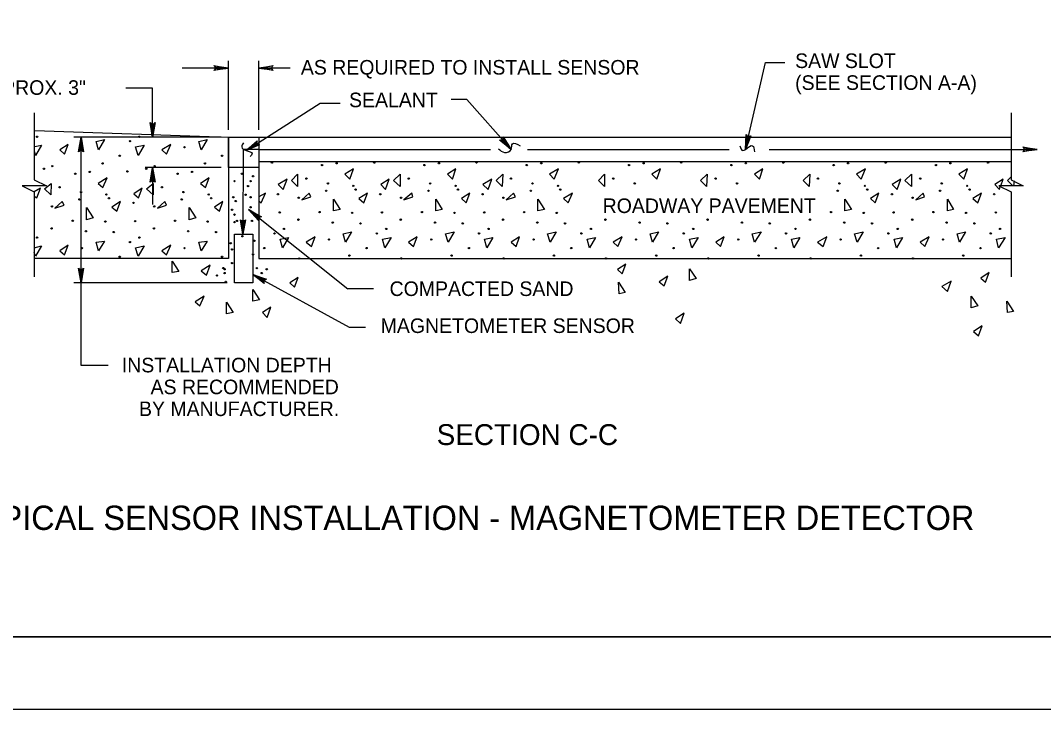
# Model space of a CAD drawing. Extents: x 2709 to 3899, y 22 to 1210.
# Drawn here: x 2819.9 to 3030.6, y 22.2 to 164.1 of the extents above; entities that cross this region are included whole.
import ezdxf

# ---------------------------------------------------------------- set-up
doc = ezdxf.new("R2010")
doc.units = 0
for name, color, linetype in [('1', 7, 'Continuous'), ('2', 7, 'Continuous'), ('3', 7, 'Continuous'), ('PLT-BNDY', 7, 'Continuous')]:
    doc.layers.add(name, color=color, linetype=linetype)

# ---------------------------------------------------------------- blocks, each defined once
blk = doc.blocks.new('RARROW')
at = {"layer": '3'}
blk.add_lwpolyline([(-2.2695, 0.285), (-2.184875, 0.12075), (0, 0), (-2.2695, 0.285), (-2.38575, 0.384625), (0, 0), (-2.183125, -0.108), (-2.262875, -0.2705), (0, 0), (-2.38575, -0.379125), (-2.262875, -0.2705)], dxfattribs=at)

msp = doc.modelspace()

# ---------------------------------------------------------------- linework, layer by layer
at = {"layer": '1'}
for p, q in [((3534.86, 37.17), (2748.86, 37.17)), ((2748.86, 37.17), (3334.86, 37.17))]:
    msp.add_line(p, q, dxfattribs=at)
at = {"layer": '2'}
for p, q in [((2862.72, 154.29), (2853.22, 154.29)), ((2862.72, 141.54), (2862.72, 155.79)), ((2868.97, 141.54), (2868.97, 155.79)), ((2875.47, 154.29), (2868.97, 154.29)), ((2969.22, 137.54), (2973.35, 155.41)), ((2973.35, 155.41), (2977.35, 155.41)), ((2847.1, 150.16), (2841.6, 150.16)), ((2847.1, 140.04), (2847.1, 150.16)), ((2911.85, 147.79), (2908.6, 147.79)), ((2920.97, 137.54), (2911.85, 147.79)), ((2866.35, 137.29), (2881.6, 147.04)), ((2881.6, 147.04), (2885.72, 147.04)), ((2861.22, 140.04), (2830.85, 140.04)), ((2832.35, 110.04), (2832.35, 140.04)), ((2861.22, 140.04), (2845.6, 140.04)), ((2868.97, 140.04), (2868.97, 115.04)), ((2861.22, 133.79), (2845.6, 133.79)), ((2847.1, 133.79), (2847.1, 126.16)), ((2866.85, 125.16), (2887.35, 108.79)), ((2867.72, 111.79), (2887.6, 100.91)), ((2862.47, 110.04), (2830.85, 110.04)), ((2832.35, 93.04), (2832.35, 110.04)), ((2892.6, 108.79), (2887.35, 108.79)), ((2887.6, 100.91), (2890.97, 100.91)), ((2837.97, 93.04), (2832.35, 93.04))]:
    msp.add_line(p, q, dxfattribs=at)
for points in [[(2822.72, 145.04), (2822.72, 131.29), (2825.22, 130.04), (2820.22, 130.04), (2822.72, 128.79), (2822.72, 111.29)], [(3023.97, 145.04), (3023.97, 131.29), (3026.47, 130.04), (3021.47, 130.04), (3023.97, 128.79), (3023.97, 111.29)], [(2822.85, 141.41), (2862.72, 140.04)], [(2862.72, 140.04), (2862.72, 115.04), (2822.72, 115.04)], [(2862.72, 140.04), (2868.97, 140.04), (2868.97, 133.79), (2862.72, 133.79), (2862.72, 140.04)], [(2868.97, 140.04), (3023.97, 140.04)], [(2822.85, 138.16), (2824.22, 138.41)], [(2822.97, 136.29), (2822.85, 137.04)], [(2824.22, 138.41), (2822.97, 136.29)], [(2868.97, 137.54), (2865.73, 137.53), (2865.72, 120.04)], [(2868.97, 137.54), (2916.72, 137.54)], [(2924.35, 137.54), (2965.85, 137.54)], [(2974.1, 137.54), (3029.35, 137.54)], [(2868.97, 135.04), (3023.97, 135.04)], [(3022.35, 131.41), (3020.6, 130.29)], [(3021.85, 130.04), (3022.35, 131.41)], [(3023.22, 131.16), (3023.97, 131.91)], [(3024.35, 130.04), (3023.22, 131.16)], [(3024.6, 131.04), (3024.47, 130.04)], [(2823.97, 129.54), (2822.72, 128.79)], [(2823.22, 127.54), (2823.97, 129.54)], [(2824.85, 129.41), (2826.22, 130.54)], [(2826.1, 128.16), (2824.85, 129.41)], [(2826.22, 130.54), (2826.1, 128.16)], [(3020.6, 130.29), (3021.6, 129.29)], [(3021.6, 129.29), (3021.72, 129.91)], [(2822.72, 127.91), (2823.22, 127.54)], [(2870.35, 128.54), (2868.97, 127.79)], [(2868.97, 126.91), (2869.47, 126.54)], [(2869.47, 126.54), (2870.35, 128.54)], [(2822.72, 117.29), (2824.22, 117.66)], [(2822.97, 115.54), (2822.72, 116.29)], [(2824.22, 117.66), (2822.97, 115.54)], [(2868.97, 115.04), (3023.97, 115.04)]]:
    msp.add_lwpolyline(points, dxfattribs=at)
for points in [[(2835.47, 139.16), (2837.22, 139.54), (2835.97, 137.41)], [(2856.6, 139.16), (2858.35, 139.54), (2857.1, 137.41)], [(2829.72, 138.54), (2827.97, 137.41), (2828.97, 136.54)], [(2843.6, 138.04), (2845.35, 138.41), (2844.1, 136.29)], [(2850.85, 138.54), (2848.97, 137.41), (2849.97, 136.54)], [(2888.47, 133.54), (2886.72, 132.41), (2887.72, 131.41)], [(2909.6, 133.54), (2907.85, 132.41), (2908.85, 131.41)], [(2930.72, 133.54), (2928.85, 132.41), (2929.85, 131.41)], [(2951.72, 133.54), (2949.97, 132.41), (2950.97, 131.41)], [(2972.85, 133.54), (2971.1, 132.41), (2972.1, 131.41)], [(2993.97, 133.54), (2992.1, 132.41), (2993.1, 131.41)], [(3014.97, 133.54), (3013.22, 132.41), (3014.22, 131.41)], [(2837.72, 131.66), (2835.85, 130.54), (2836.85, 129.66)], [(2858.72, 131.66), (2856.97, 130.54), (2857.97, 129.66)], [(2874.85, 131.41), (2872.97, 130.29), (2873.97, 129.29)], [(2875.72, 131.16), (2876.97, 132.41), (2876.97, 129.91)], [(2895.85, 131.41), (2894.1, 130.29), (2895.1, 129.29)], [(2896.72, 131.16), (2898.1, 132.41), (2898.1, 129.91)], [(2916.97, 131.41), (2915.1, 130.29), (2916.22, 129.29)], [(2917.85, 131.16), (2919.22, 132.41), (2919.1, 129.91)], [(2938.97, 131.16), (2940.22, 132.41), (2940.22, 129.91)], [(2959.97, 131.16), (2961.35, 132.41), (2961.22, 129.91)], [(2981.1, 131.16), (2982.47, 132.41), (2982.35, 129.91)], [(3001.22, 131.41), (2999.47, 130.29), (3000.47, 129.29)], [(3002.1, 131.16), (3003.47, 132.41), (3003.47, 129.91)], [(2844.97, 129.54), (2843.22, 128.41), (2844.22, 127.54)], [(2845.85, 129.41), (2847.22, 130.54), (2847.22, 128.16)], [(2828.85, 126.04), (2828.47, 126.79), (2826.97, 125.41)], [(2840.47, 126.79), (2838.72, 125.66), (2839.72, 124.79)], [(2849.97, 126.04), (2849.6, 126.79), (2848.1, 125.41)], [(2861.6, 126.79), (2859.85, 125.66), (2860.85, 124.79)], [(2879.72, 127.79), (2879.35, 128.54), (2877.85, 127.16)], [(2885.72, 125.16), (2884.35, 124.91), (2884.35, 127.29)], [(2891.35, 128.54), (2889.6, 127.41), (2890.6, 126.54)], [(2900.72, 127.79), (2900.47, 128.54), (2898.85, 127.16)], [(2906.72, 125.16), (2905.47, 124.91), (2905.47, 127.29)], [(2912.47, 128.54), (2910.72, 127.41), (2911.72, 126.54)], [(2921.85, 127.79), (2921.47, 128.54), (2919.97, 127.16)], [(2927.85, 125.16), (2926.47, 124.91), (2926.47, 127.29)], [(2933.6, 128.54), (2931.72, 127.41), (2932.72, 126.54)], [(2991.1, 125.16), (2989.72, 124.91), (2989.72, 127.29)], [(2996.72, 128.54), (2994.97, 127.41), (2995.97, 126.54)], [(3006.1, 127.79), (3005.85, 128.54), (3004.35, 127.16)], [(3012.1, 125.16), (3010.85, 124.91), (3010.85, 127.29)], [(3017.85, 128.54), (3016.1, 127.41), (3017.1, 126.54)], [(2834.85, 123.41), (2833.47, 123.04), (2833.47, 125.54)], [(2855.97, 123.41), (2854.6, 123.04), (2854.6, 125.54)], [(2886.35, 120.16), (2888.1, 120.54), (2886.85, 118.41)], [(2907.47, 120.16), (2909.22, 120.54), (2907.97, 118.41)], [(2928.47, 120.16), (2930.22, 120.54), (2928.97, 118.41)], [(2949.6, 120.16), (2951.35, 120.54), (2950.1, 118.41)], [(2970.6, 120.16), (2972.47, 120.54), (2971.1, 118.41)], [(2991.72, 120.16), (2993.47, 120.54), (2992.22, 118.41)], [(3012.85, 120.16), (3014.6, 120.54), (3013.35, 118.41)], [(2835.47, 118.41), (2837.22, 118.66), (2835.97, 116.66)], [(2856.6, 118.41), (2858.35, 118.66), (2857.1, 116.66)], [(2867.72, 120.04), (2867.72, 110.04), (2863.97, 110.04), (2863.97, 120.04)], [(2873.35, 119.04), (2875.1, 119.41), (2873.85, 117.29)], [(2880.6, 119.54), (2878.72, 118.41), (2879.85, 117.54)], [(2894.47, 119.04), (2896.22, 119.41), (2894.97, 117.29)], [(2901.6, 119.54), (2899.85, 118.41), (2900.85, 117.54)], [(2915.47, 119.04), (2917.22, 119.41), (2915.97, 117.29)], [(2922.72, 119.54), (2920.97, 118.41), (2921.97, 117.54)], [(2936.6, 119.04), (2938.35, 119.41), (2937.1, 117.29)], [(2943.85, 119.54), (2941.97, 118.41), (2942.97, 117.54)], [(2957.72, 119.04), (2959.47, 119.41), (2958.22, 117.29)], [(2964.85, 119.54), (2963.1, 118.41), (2964.1, 117.54)], [(2978.72, 119.04), (2980.47, 119.41), (2979.22, 117.29)], [(2985.97, 119.54), (2984.1, 118.41), (2985.22, 117.54)], [(2999.85, 119.04), (3001.6, 119.41), (3000.35, 117.29)], [(3007.1, 119.54), (3005.22, 118.41), (3006.22, 117.54)], [(3020.97, 119.04), (3022.72, 119.41), (3021.35, 117.29)], [(2829.72, 117.79), (2827.97, 116.66), (2828.97, 115.79)], [(2843.6, 117.29), (2845.35, 117.66), (2844.1, 115.54)], [(2850.85, 117.79), (2848.97, 116.66), (2849.97, 115.79)], [(2852.47, 112.41), (2851.1, 112.16), (2851.1, 114.54)], [(2944.6, 113.91), (2942.85, 112.79), (2943.85, 111.91)], [(2858.97, 113.66), (2857.1, 112.54), (2858.22, 111.66)], [(2959.1, 110.91), (2957.72, 110.54), (2957.72, 112.91)], [(3019.47, 112.16), (3017.72, 111.04), (3018.72, 110.16)], [(2877.1, 111.16), (2875.35, 110.04), (2876.35, 109.16)], [(2944.47, 108.04), (2943.22, 107.79), (2943.1, 110.16)], [(2953.22, 111.41), (2951.47, 110.29), (2952.47, 109.41)], [(3011.6, 110.41), (3009.72, 109.29), (3010.85, 108.29)], [(2869.1, 106.54), (2867.72, 106.29), (2867.72, 108.66)], [(2857.72, 107.29), (2855.85, 106.16), (2856.85, 105.29)], [(2863.72, 103.91), (2862.35, 103.66), (2862.35, 106.04)], [(3017.1, 105.29), (3015.72, 104.91), (3015.72, 107.29)], [(3024.47, 104.16), (3023.22, 103.91), (3023.1, 106.29)], [(2871.47, 105.04), (2869.72, 103.91), (2870.72, 102.91)], [(2956.6, 103.79), (2954.85, 102.66), (2955.85, 101.66)], [(3017.97, 101.16), (3016.22, 100.04), (3017.22, 99.16)]]:
    msp.add_lwpolyline(points, close=True, dxfattribs=at)
for centre in [(2823.31, 140.15), (2842.44, 139.23), (2844.39, 140.15), (2832.59, 137.97), (2853.67, 137.97), (2840.34, 136.22), (2861.42, 136.22), (2871.67, 134.8), (2892.75, 134.8), (2913.83, 134.8), (2934.91, 134.8), (2955.99, 134.8), (2977.06, 134.8), (2998.14, 134.8), (3019.22, 134.8), (2824.72, 133.54), (2826.44, 134.08), (2834.15, 132.9), (2836.79, 134.65), (2841.9, 133.01), (2845.8, 133.54), (2847.52, 134.08), (2855.23, 132.9), (2857.87, 134.65), (2882.02, 134.3), (2885, 134.68), (2903.1, 134.3), (2906.08, 134.68), (2924.18, 134.3), (2927.16, 134.68), (2945.26, 134.3), (2948.24, 134.68), (2966.34, 134.3), (2969.31, 134.68), (2987.41, 134.3), (2990.39, 134.68), (3008.49, 134.3), (3011.47, 134.68), (2831.17, 132.51), (2852.25, 132.51), (2863.97, 130.99), (2865.5, 132.52), (2867.29, 130.99), (2867.8, 132.01), (2878.78, 131.52), (2899.86, 131.52), (2920.93, 131.52), (2942.01, 131.52), (2963.09, 131.52), (2984.17, 131.52), (3005.25, 131.52), (2827.93, 129.73), (2832.36, 128.73), (2849.01, 129.73), (2853.44, 128.73), (2866.78, 129.97), (2882.86, 129.02), (2883.21, 130.52), (2888.44, 130.03), (2888.93, 129.25), (2903.94, 129.02), (2904.28, 130.52), (2909.52, 130.03), (2910.01, 129.25), (2925.02, 129.02), (2925.36, 130.52), (2930.59, 130.03), (2931.09, 129.25), (2946.44, 130.52), (2967.52, 130.52), (2988.25, 129.02), (2988.6, 130.52), (2993.83, 130.03), (2994.32, 129.25), (3009.33, 129.02), (3009.68, 130.52), (3014.91, 130.03), (3015.4, 129.25), (2832.01, 127.23), (2837.59, 128.24), (2838.09, 127.46), (2843.16, 126.5), (2853.09, 127.23), (2858.67, 128.24), (2859.16, 127.46), (2863.71, 127.67), (2864.22, 126.9), (2866.27, 128.18), (2867.29, 127.67), (2872.93, 128.29), (2877.21, 127.57), (2894.01, 128.29), (2898.29, 127.57), (2915.09, 128.29), (2919.37, 127.57), (2999.4, 128.29), (3003.68, 127.57), (3020.48, 128.29), (2826.36, 125.78), (2847.44, 125.78), (2863.46, 125.11), (2867.29, 125.62), (2873.28, 124.55), (2881.49, 124.63), (2888.21, 124.44), (2894.35, 124.55), (2902.57, 124.63), (2909.29, 124.44), (2915.43, 124.55), (2923.65, 124.63), (2930.36, 124.44), (2986.88, 124.63), (2993.6, 124.44), (2999.75, 124.55), (3007.96, 124.63), (3014.68, 124.44), (3020.82, 124.55), (2830.64, 122.84), (2837.36, 122.65), (2843.51, 122.76), (2851.72, 122.84), (2858.44, 122.65), (2863.97, 124.09), (2863.97, 122.56), (2864.48, 122.81), (2867.55, 122.81), (2877.14, 123.06), (2884.2, 122.45), (2889.93, 122.3), (2898.21, 123.06), (2905.28, 122.45), (2911, 122.3), (2919.29, 123.06), (2926.36, 122.45), (2932.08, 122.3), (2940.37, 123.06), (2947.43, 122.45), (2953.16, 122.3), (2961.45, 123.06), (2968.51, 122.45), (2974.24, 122.3), (2982.53, 123.06), (2989.59, 122.45), (2995.32, 122.3), (3003.61, 123.06), (3010.67, 122.45), (3016.4, 122.3), (2826.29, 121.27), (2833.35, 120.66), (2839.08, 120.51), (2847.37, 121.27), (2854.43, 120.66), (2860.16, 120.51), (2872.21, 120.24), (2874.15, 121.15), (2893.29, 120.24), (2895.23, 121.15), (2914.36, 120.24), (2916.31, 121.15), (2935.44, 120.24), (2937.39, 121.15), (2956.52, 120.24), (2958.47, 121.15), (2977.6, 120.24), (2979.55, 121.15), (2998.68, 120.24), (3000.62, 121.15), (3019.76, 120.24), (3021.7, 121.15), (2823.31, 119.36), (2842.44, 118.45), (2844.39, 119.36), (2863.2, 118.21), (2865.59, 119.65), (2868.06, 118.72), (2883.44, 118.98), (2904.51, 118.98), (2925.59, 118.98), (2946.67, 118.98), (2967.75, 118.98), (2988.83, 118.98), (3009.91, 118.98), (2832.59, 117.19), (2853.67, 117.19), (2863.46, 116.93), (2867.8, 115.91), (2870.11, 117.22), (2891.19, 117.22), (2912.26, 117.22), (2933.34, 117.22), (2954.42, 117.22), (2975.5, 117.22), (2996.58, 117.22), (3017.66, 117.22), (2840.34, 115.43), (2861.42, 115.43), (2863.46, 114.12), (2877.29, 115.08), (2887.64, 115.66), (2898.37, 115.08), (2908.71, 115.66), (2919.45, 115.08), (2929.79, 115.66), (2940.52, 115.08), (2950.87, 115.66), (2961.6, 115.08), (2971.95, 115.66), (2982.68, 115.08), (2993.03, 115.66), (3003.76, 115.08), (3014.1, 115.66), (2861.67, 113.1), (2861.92, 112.84), (2861.92, 112.07), (2868.57, 113.1), (2869.59, 112.07), (2870.61, 112.84), (2860.39, 111.56), (2862.18, 110.28)]:
    msp.add_circle(centre, 0.138, dxfattribs=at)
for points in [[(2865.85, 138.91), (2865.47, 138.04), (2866.35, 137.29), (2867.6, 136.66), (2867.22, 136.04)], [(2918.35, 137.66), (2919.6, 136.91), (2920.97, 137.54), (2921.22, 138.66), (2922.85, 138.29)], [(2968.1, 138.29), (2968.72, 137.29), (2969.22, 137.54), (2970.72, 138.29), (2971.1, 137.04)]]:
    msp.add_spline(points, degree=3, dxfattribs=at)
at = {"layer": 'PLT-BNDY'}
msp.add_lwpolyline([(2708.86, 616.17), (3549.86, 616.17), (3549.86, 22.17), (2708.86, 22.17)], close=True, dxfattribs=at)

# ---------------------------------------------------------------- block references
at = {"layer": '2', "xscale": 1.2574347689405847, "yscale": 1.3092961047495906}
for p in [(2862.72, 154.29), (3029.35, 137.54)]:
    msp.add_blockref('RARROW', p, dxfattribs=at)
at = {"layer": '2'}
for p, xscale, yscale, rotation in [((2868.97, 154.29), 1.2574347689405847, 1.3092961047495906, 180), ((2847.1, 140.04), 1.2574347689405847, 1.3092961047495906, -90.00000000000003), ((2832.35, 140.04), 1.2574347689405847, 1.3092961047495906, 89.99999999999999), ((2866.35, 137.29), 1.2574347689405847, 1.3092961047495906, -147.37682038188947), ((2920.97, 137.54), 1.2574347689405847, 1.3092961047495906, -48.04050068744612), ((2969.22, 137.54), 1.257434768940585, 1.3092961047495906, -102.5390809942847), ((2847.1, 133.79), 1.2574347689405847, 1.3092961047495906, 89.99999999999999), ((2866.85, 125.16), 1.2574347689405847, 1.3092961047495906, 141.4101849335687), ((2865.72, 120.04), 1.2574347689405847, 1.3092961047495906, -90.00000000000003), ((2832.35, 110.04), 1.2574347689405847, 1.3092961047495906, -90.00000000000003), ((2867.72, 111.79), 1.2574347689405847, 1.3092961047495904, 151.32018881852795)]:
    msp.add_blockref('RARROW', p, dxfattribs=dict(at, xscale=xscale, yscale=yscale, rotation=rotation))

# ---------------------------------------------------------------- texts
for s, height, p in [('AS REQUIRED TO INSTALL SENSOR', 3, (2877.64, 152.94)), ('SAW SLOT', 3, (2979.47, 154.29)), ('APPROX. 3"', 3, (2810.75, 148.77)), ('(SEE SECTION A-A)', 3, (2979.47, 149.79)), ('SEALANT', 3, (2887.57, 146.22)), ('ROADWAY PAVEMENT', 3, (2939.82, 124.43)), ('COMPACTED SAND', 3, (2895.92, 107.34)), ('MAGNETOMETER SENSOR', 3, (2894.08, 99.72)), ('INSTALLATION DEPTH', 3, (2840.76, 91.61)), ('AS RECOMMENDED', 3, (2846.68, 87.11)), ('BY MANUFACTURER.', 3, (2844.3, 82.61)), ('SECTION C-C', 4.3, (2905.62, 76.64)), ('TYPICAL SENSOR INSTALLATION - MAGNETOMETER DETECTOR', 5, (2807.23, 59.16))]:
    msp.add_text(s, height=height, dxfattribs=at).set_placement(p)

doc.saveas('drawing.dxf')
